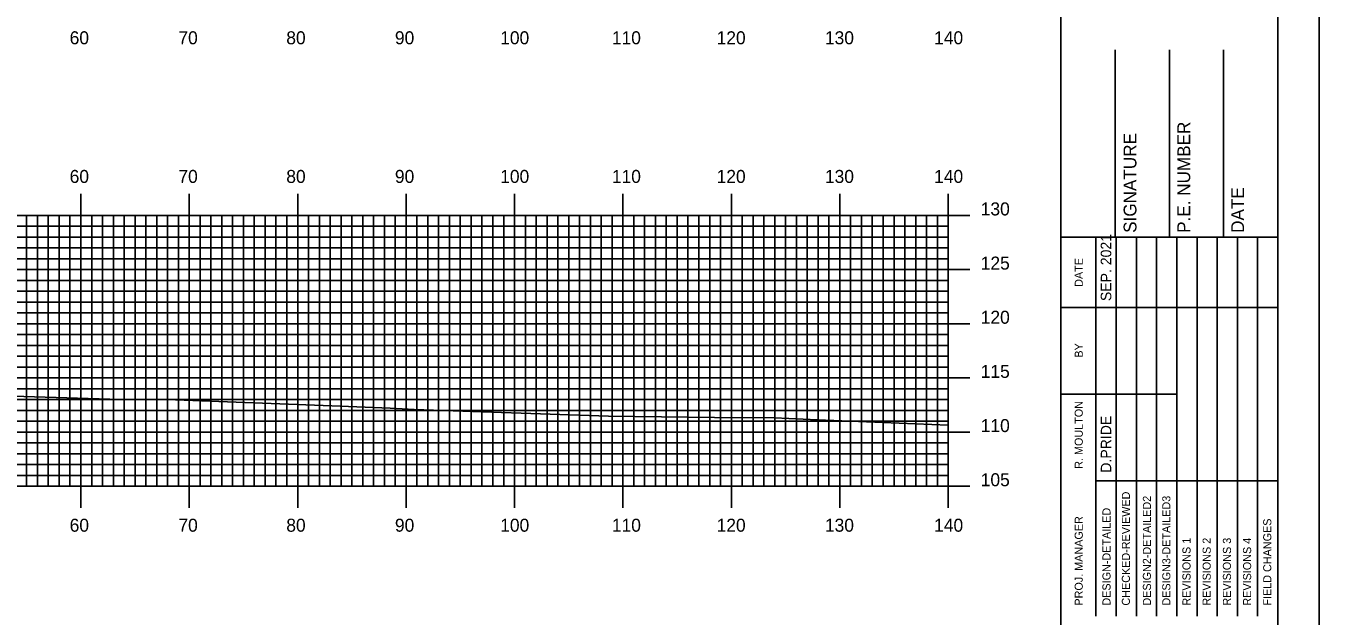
# Model space of a CAD drawing. Extents: x 1771235 to 1771579, y 442591 to 442811.
# Drawn here: x 1771456 to 1771575.3, y 442686.7 to 442741.2 of the extents above; entities that cross this region are included whole.
import ezdxf

# ---------------------------------------------------------------- set-up
doc = ezdxf.new("R2010")
doc.units = 0
for name, color, linetype in [('BORDER', 7, 'Continuous'), ('H_V ANNOTATION', 7, 'Continuous'), ('MAJOR', 7, 'Continuous'), ('MINOR', 7, 'Continuous'), ('PLOT BOUNDARY', 7, 'Continuous'), ('S_Roadway_Centerline', 7, 'Continuous')]:
    doc.layers.add(name, color=color, linetype=linetype)

msp = doc.modelspace()

# ---------------------------------------------------------------- linework, layer by layer
at = {"layer": 'BORDER'}
for p, q in [((1771551.47, 442596.67), (1771551.47, 442806.67)), ((1771556.47, 442721.67), (1771556.47, 442738.97)), ((1771561.47, 442721.67), (1771561.47, 442738.97)), ((1771566.47, 442721.67), (1771566.47, 442738.97)), ((1771551.47, 442721.67), (1771571.47, 442721.67))]:
    msp.add_line(p, q, dxfattribs=at)
msp.add_lwpolyline([(1771251.47, 442596.67), (1771571.47, 442596.67), (1771571.47, 442806.67), (1771251.47, 442806.67)], close=True, dxfattribs=at)
for points in [[(1771554.7, 442715.17), (1771554.7, 442721.67)], [(1771556.56, 442686.68), (1771556.56, 442721.67)], [(1771558.43, 442721.67), (1771558.43, 442686.68)], [(1771560.29, 442686.68), (1771560.29, 442721.67)], [(1771562.15, 442686.68), (1771562.15, 442721.67)], [(1771564.02, 442686.68), (1771564.02, 442721.67)], [(1771565.88, 442686.68), (1771565.88, 442721.67)], [(1771567.74, 442686.68), (1771567.74, 442721.67)], [(1771569.61, 442686.68), (1771569.61, 442721.67)], [(1771554.7, 442686.68), (1771554.7, 442720.26)], [(1771551.47, 442715.17), (1771571.47, 442715.17)], [(1771551.47, 442707.17), (1771554.7, 442707.17)], [(1771554.7, 442707.17), (1771562.15, 442707.17)], [(1771554.7, 442699.17), (1771571.47, 442699.17)]]:
    msp.add_lwpolyline(points, dxfattribs=at)
at = {"layer": 'MAJOR'}
for p, q in [((1771461.07, 442725.67), (1771461.07, 442723.67)), ((1771471.07, 442725.67), (1771471.07, 442723.67)), ((1771481.07, 442725.67), (1771481.07, 442723.67)), ((1771491.07, 442725.67), (1771491.07, 442723.67)), ((1771501.07, 442725.67), (1771501.07, 442723.67)), ((1771511.07, 442725.67), (1771511.07, 442723.67)), ((1771521.07, 442725.67), (1771521.07, 442723.67)), ((1771531.07, 442725.67), (1771531.07, 442723.67)), ((1771541.07, 442725.67), (1771541.07, 442723.67)), ((1771261.07, 442723.67), (1771541.07, 442723.67)), ((1771261.07, 442723.67), (1771541.07, 442723.67)), ((1771461.07, 442698.67), (1771461.07, 442723.67)), ((1771471.07, 442698.67), (1771471.07, 442723.67)), ((1771481.07, 442698.67), (1771481.07, 442723.67)), ((1771491.07, 442698.67), (1771491.07, 442723.67)), ((1771501.07, 442698.67), (1771501.07, 442723.67)), ((1771511.07, 442698.67), (1771511.07, 442723.67)), ((1771521.07, 442698.67), (1771521.07, 442723.67)), ((1771531.07, 442698.67), (1771531.07, 442723.67)), ((1771543.07, 442723.67), (1771539.06, 442723.67)), ((1771541.07, 442698.67), (1771541.07, 442723.67)), ((1771541.07, 442698.67), (1771541.07, 442723.67)), ((1771261.07, 442718.67), (1771541.07, 442718.67)), ((1771543.07, 442718.67), (1771539.06, 442718.67)), ((1771261.07, 442713.67), (1771541.07, 442713.67)), ((1771543.07, 442713.67), (1771539.06, 442713.67)), ((1771261.07, 442708.67), (1771541.07, 442708.67)), ((1771543.07, 442708.67), (1771539.06, 442708.67)), ((1771261.07, 442703.67), (1771541.07, 442703.67)), ((1771543.07, 442703.67), (1771539.06, 442703.67)), ((1771261.07, 442698.67), (1771541.07, 442698.67)), ((1771261.07, 442698.67), (1771541.07, 442698.67)), ((1771461.07, 442696.66), (1771461.07, 442698.67)), ((1771471.07, 442696.66), (1771471.07, 442698.67)), ((1771481.07, 442696.66), (1771481.07, 442698.67)), ((1771491.07, 442696.66), (1771491.07, 442698.67)), ((1771501.07, 442696.66), (1771501.07, 442698.67)), ((1771511.07, 442696.66), (1771511.07, 442698.67)), ((1771521.07, 442696.66), (1771521.07, 442698.67)), ((1771531.07, 442696.66), (1771531.07, 442698.67)), ((1771543.07, 442698.67), (1771539.06, 442698.67)), ((1771541.07, 442696.66), (1771541.07, 442698.67))]:
    msp.add_line(p, q, dxfattribs=at)
at = {"layer": 'MINOR'}
for p, q in [((1771456.07, 442698.67), (1771456.07, 442723.67)), ((1771457.07, 442698.67), (1771457.07, 442723.67)), ((1771458.07, 442698.67), (1771458.07, 442723.67)), ((1771459.07, 442698.67), (1771459.07, 442723.67)), ((1771460.07, 442698.67), (1771460.07, 442723.67)), ((1771462.07, 442698.67), (1771462.07, 442723.67)), ((1771463.07, 442698.67), (1771463.07, 442723.67)), ((1771464.07, 442698.67), (1771464.07, 442723.67)), ((1771465.07, 442698.67), (1771465.07, 442723.67)), ((1771466.07, 442698.67), (1771466.07, 442723.67)), ((1771467.07, 442698.67), (1771467.07, 442723.67)), ((1771468.07, 442698.67), (1771468.07, 442723.67)), ((1771469.07, 442698.67), (1771469.07, 442723.67)), ((1771470.07, 442698.67), (1771470.07, 442723.67)), ((1771472.07, 442698.67), (1771472.07, 442723.67)), ((1771473.07, 442698.67), (1771473.07, 442723.67)), ((1771474.07, 442698.67), (1771474.07, 442723.67)), ((1771475.07, 442698.67), (1771475.07, 442723.67)), ((1771476.07, 442698.67), (1771476.07, 442723.67)), ((1771477.07, 442698.67), (1771477.07, 442723.67)), ((1771478.07, 442698.67), (1771478.07, 442723.67)), ((1771479.07, 442698.67), (1771479.07, 442723.67)), ((1771480.07, 442698.67), (1771480.07, 442723.67)), ((1771482.07, 442698.67), (1771482.07, 442723.67)), ((1771483.07, 442698.67), (1771483.07, 442723.67)), ((1771484.07, 442698.67), (1771484.07, 442723.67)), ((1771485.07, 442698.67), (1771485.07, 442723.67)), ((1771486.07, 442698.67), (1771486.07, 442723.67)), ((1771487.07, 442698.67), (1771487.07, 442723.67)), ((1771488.07, 442698.67), (1771488.07, 442723.67)), ((1771489.07, 442698.67), (1771489.07, 442723.67)), ((1771490.07, 442698.67), (1771490.07, 442723.67)), ((1771492.07, 442698.67), (1771492.07, 442723.67)), ((1771493.07, 442698.67), (1771493.07, 442723.67)), ((1771494.07, 442698.67), (1771494.07, 442723.67)), ((1771495.07, 442698.67), (1771495.07, 442723.67)), ((1771496.07, 442698.67), (1771496.07, 442723.67)), ((1771497.07, 442698.67), (1771497.07, 442723.67)), ((1771498.07, 442698.67), (1771498.07, 442723.67)), ((1771499.07, 442698.67), (1771499.07, 442723.67)), ((1771500.07, 442698.67), (1771500.07, 442723.67)), ((1771502.07, 442698.67), (1771502.07, 442723.67)), ((1771503.07, 442698.67), (1771503.07, 442723.67)), ((1771504.07, 442698.67), (1771504.07, 442723.67)), ((1771505.07, 442698.67), (1771505.07, 442723.67)), ((1771506.07, 442698.67), (1771506.07, 442723.67)), ((1771507.07, 442698.67), (1771507.07, 442723.67)), ((1771508.07, 442698.67), (1771508.07, 442723.67)), ((1771509.07, 442698.67), (1771509.07, 442723.67)), ((1771510.07, 442698.67), (1771510.07, 442723.67)), ((1771512.07, 442698.67), (1771512.07, 442723.67)), ((1771513.07, 442698.67), (1771513.07, 442723.67)), ((1771514.07, 442698.67), (1771514.07, 442723.67)), ((1771515.07, 442698.67), (1771515.07, 442723.67)), ((1771516.07, 442698.67), (1771516.07, 442723.67)), ((1771517.07, 442698.67), (1771517.07, 442723.67)), ((1771518.07, 442698.67), (1771518.07, 442723.67)), ((1771519.07, 442698.67), (1771519.07, 442723.67)), ((1771520.07, 442698.67), (1771520.07, 442723.67)), ((1771522.07, 442698.67), (1771522.07, 442723.67)), ((1771523.07, 442698.67), (1771523.07, 442723.67)), ((1771524.07, 442698.67), (1771524.07, 442723.67)), ((1771525.07, 442698.67), (1771525.07, 442723.67)), ((1771526.07, 442698.67), (1771526.07, 442723.67)), ((1771527.07, 442698.67), (1771527.07, 442723.67)), ((1771528.07, 442698.67), (1771528.07, 442723.67)), ((1771529.07, 442698.67), (1771529.07, 442723.67)), ((1771530.07, 442698.67), (1771530.07, 442723.67)), ((1771532.07, 442698.67), (1771532.07, 442723.67)), ((1771533.07, 442698.67), (1771533.07, 442723.67)), ((1771534.07, 442698.67), (1771534.07, 442723.67)), ((1771535.07, 442698.67), (1771535.07, 442723.67)), ((1771536.07, 442698.67), (1771536.07, 442723.67)), ((1771537.07, 442698.67), (1771537.07, 442723.67)), ((1771538.07, 442698.67), (1771538.07, 442723.67)), ((1771539.07, 442698.67), (1771539.07, 442723.67)), ((1771540.07, 442698.67), (1771540.07, 442723.67)), ((1771261.07, 442722.67), (1771541.07, 442722.67)), ((1771541.07, 442722.67), (1771539.06, 442722.67)), ((1771261.07, 442721.67), (1771541.07, 442721.67)), ((1771261.07, 442720.67), (1771541.07, 442720.67)), ((1771541.07, 442721.67), (1771539.06, 442721.67)), ((1771541.07, 442720.67), (1771539.06, 442720.67)), ((1771261.07, 442719.67), (1771541.07, 442719.67)), ((1771541.07, 442719.67), (1771539.06, 442719.67)), ((1771261.07, 442717.67), (1771541.07, 442717.67)), ((1771541.07, 442717.67), (1771539.06, 442717.67)), ((1771261.07, 442716.67), (1771541.07, 442716.67)), ((1771541.07, 442716.67), (1771539.06, 442716.67)), ((1771261.07, 442715.67), (1771541.07, 442715.67)), ((1771261.07, 442714.67), (1771541.07, 442714.67)), ((1771541.07, 442715.67), (1771539.06, 442715.67)), ((1771541.07, 442714.67), (1771539.06, 442714.67)), ((1771261.07, 442712.67), (1771541.07, 442712.67)), ((1771541.07, 442712.67), (1771539.06, 442712.67)), ((1771261.07, 442711.67), (1771541.07, 442711.67)), ((1771541.07, 442711.67), (1771539.06, 442711.67)), ((1771261.07, 442710.67), (1771541.07, 442710.67)), ((1771541.07, 442710.67), (1771539.06, 442710.67)), ((1771261.07, 442709.67), (1771541.07, 442709.67)), ((1771541.07, 442709.67), (1771539.06, 442709.67)), ((1771261.07, 442707.67), (1771541.07, 442707.67)), ((1771541.07, 442707.67), (1771539.06, 442707.67)), ((1771261.07, 442706.67), (1771541.07, 442706.67)), ((1771541.07, 442706.67), (1771539.06, 442706.67)), ((1771261.07, 442705.67), (1771541.07, 442705.67)), ((1771541.07, 442705.67), (1771539.06, 442705.67)), ((1771261.07, 442704.67), (1771541.07, 442704.67)), ((1771541.07, 442704.67), (1771539.06, 442704.67)), ((1771261.07, 442702.67), (1771541.07, 442702.67)), ((1771261.07, 442701.67), (1771541.07, 442701.67)), ((1771541.07, 442702.67), (1771539.06, 442702.67)), ((1771541.07, 442701.67), (1771539.06, 442701.67)), ((1771261.07, 442700.67), (1771541.07, 442700.67)), ((1771541.07, 442700.67), (1771539.06, 442700.67)), ((1771261.07, 442699.67), (1771541.07, 442699.67)), ((1771541.07, 442699.67), (1771539.06, 442699.67))]:
    msp.add_line(p, q, dxfattribs=at)
at = {"layer": 'PLOT BOUNDARY'}
msp.add_lwpolyline([(1771235.28, 442590.55), (1771575.28, 442590.55), (1771575.28, 442810.55), (1771235.28, 442810.55)], close=True, dxfattribs=at)
at = {"layer": 'S_Roadway_Centerline'}
msp.add_lwpolyline([(1771448.82, 442707.16), (1771463.73, 442706.72), (1771469.81, 442706.63), (1771484.21, 442706.08), (1771489.6, 442705.88), (1771491.8, 442705.75), (1771509.75, 442705.13), (1771519.52, 442705.01), (1771525.06, 442704.99), (1771529, 442704.81), (1771541.07, 442704.31)], dxfattribs=at)

# ---------------------------------------------------------------- texts
at = {"layer": 'BORDER'}
for s, height, p in [('P.E. NUMBER', 1.1811, (1771563.39, 442722.06)), ('SIGNATURE', 1.181, (1771558.43, 442722.06)), ('DATE', 1.181, (1771568.35, 442722.06)), ('SEP. 2021', 0.969, (1771556.11, 442715.76)), ('DATE', 0.743, (1771553.48, 442717.08)), ('BY', 0.743, (1771553.48, 442710.54)), ('R. MOULTON', 0.745, (1771553.48, 442700.28)), ('D.PRIDE', 0.969, (1771556.11, 442699.92)), ('CHECKED-REVIEWED', 0.7455, (1771557.83, 442687.65)), ('DESIGN2-DETAILED2', 0.7455, (1771559.77, 442687.65)), ('DESIGN3-DETAILED3', 0.7455, (1771561.56, 442687.65)), ('PROJ. MANAGER', 0.7455, (1771553.48, 442687.65)), ('DESIGN-DETAILED', 0.7455, (1771556.04, 442687.65)), ('FIELD CHANGES', 0.7455, (1771570.87, 442687.65)), ('REVISIONS 1', 0.7455, (1771563.42, 442687.65)), ('REVISIONS 2', 0.7455, (1771565.28, 442687.65)), ('REVISIONS 3', 0.7455, (1771567.15, 442687.65)), ('REVISIONS 4', 0.7455, (1771569.01, 442687.65))]:
    msp.add_text(s, height=height, rotation=90, dxfattribs=at).set_placement(p)
at = {"layer": 'H_V ANNOTATION'}
for s, p in [('60', (1771460.04, 442739.47)), ('70', (1771470.07, 442739.47)), ('80', (1771480.02, 442739.47)), ('90', (1771490.04, 442739.47)), ('100', (1771499.75, 442739.47)), ('110', (1771510.05, 442739.47)), ('120', (1771519.71, 442739.47)), ('130', (1771529.7, 442739.47)), ('140', (1771539.77, 442739.47)), ('60', (1771460.04, 442726.67)), ('70', (1771470.07, 442726.67)), ('80', (1771480.02, 442726.67)), ('90', (1771490.04, 442726.67)), ('100', (1771499.75, 442726.67)), ('110', (1771510.05, 442726.67)), ('120', (1771519.71, 442726.67)), ('130', (1771529.7, 442726.67)), ('140', (1771539.77, 442726.67)), ('130', (1771544.07, 442723.67)), ('125', (1771544.07, 442718.67)), ('120', (1771544.07, 442713.67)), ('115', (1771544.07, 442708.67)), ('110', (1771544.07, 442703.67)), ('105', (1771544.07, 442698.67)), ('60', (1771460.04, 442694.47)), ('70', (1771470.07, 442694.47)), ('80', (1771480.02, 442694.47)), ('90', (1771490.04, 442694.47)), ('100', (1771499.75, 442694.47)), ('110', (1771510.05, 442694.47)), ('120', (1771519.71, 442694.47)), ('130', (1771529.7, 442694.47)), ('140', (1771539.77, 442694.47))]:
    msp.add_text(s, height=1.2, dxfattribs=at).set_placement(p)

doc.saveas('drawing.dxf')
